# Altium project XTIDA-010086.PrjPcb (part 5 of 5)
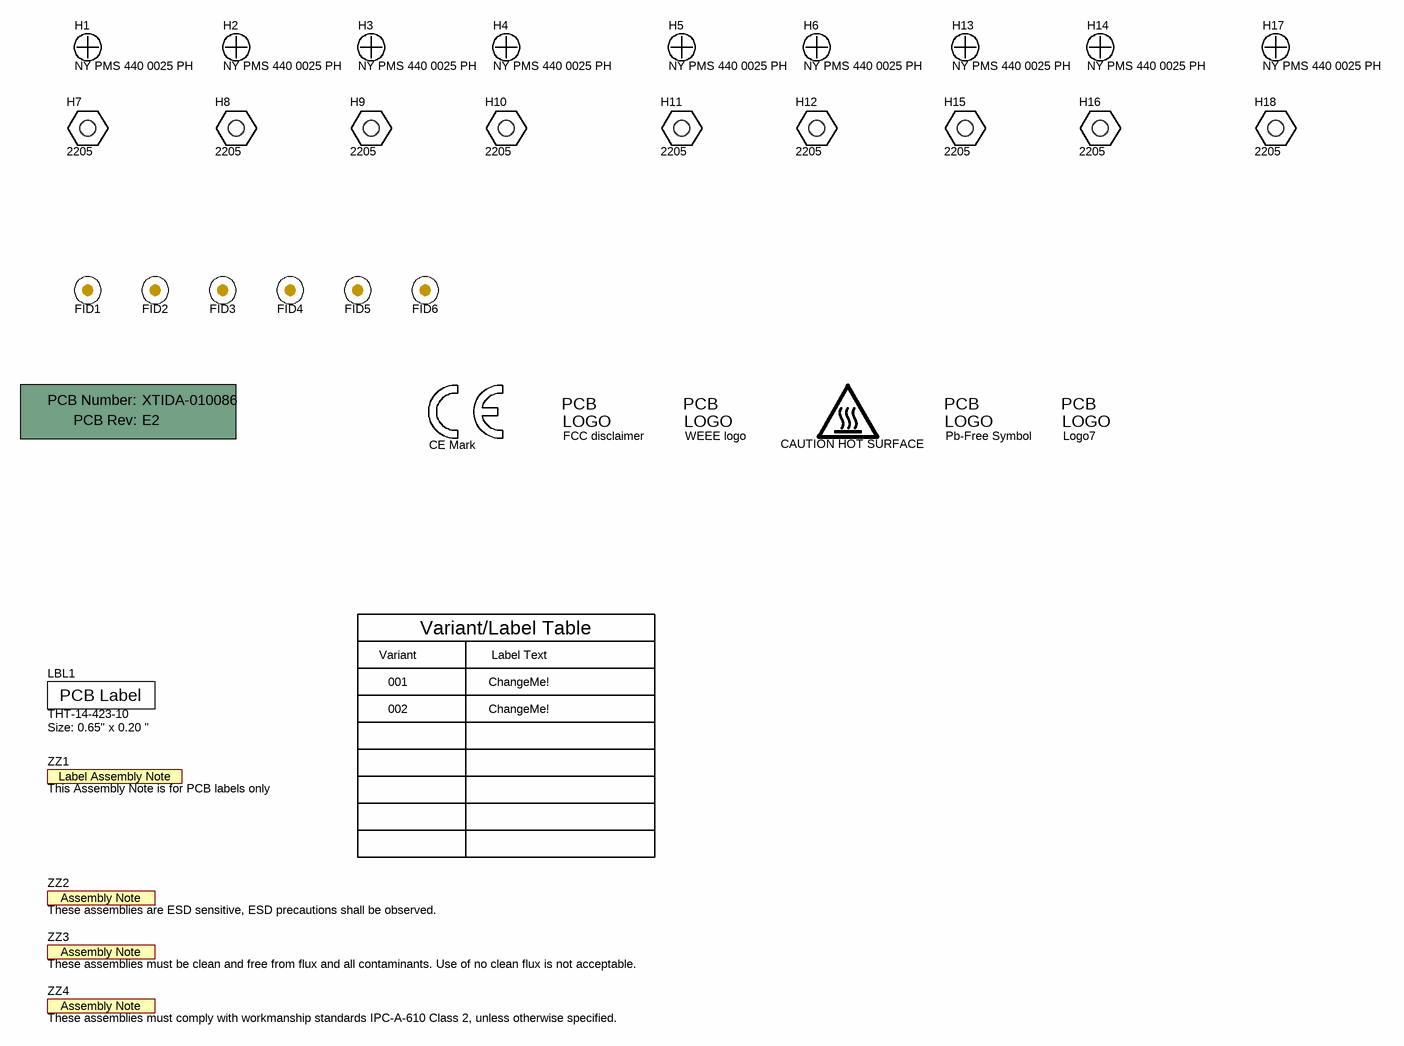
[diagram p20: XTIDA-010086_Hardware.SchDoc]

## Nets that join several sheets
2P5V: MAIN SHEET/Ch1 (C30_Ch1.1 C31_Ch1.1 U4_Ch1.3), MAIN SHEET/Ch2 (C30_Ch2.1 C31_Ch2.1 U4_Ch2.3), MAIN SHEET/Ch3 (C30_Ch3.1 C31_Ch3.1 U4_Ch3.3), MAIN SHEET/Ch4 (C30_Ch4.1 C31_Ch4.1 U4_Ch4.3), MAIN SHEET/Ch5 (C30_Ch5.1 C31_Ch5.1 U4_Ch5.3), MAIN SHEET/Ch6 (C30_Ch6.1 C31_Ch6.1 U4_Ch6.3), MAIN SHEET/Ch7 (C30_Ch7.1 C31_Ch7.1 U4_Ch7.3), MAIN SHEET/Ch8 (C30_Ch8.1 C31_Ch8.1 U4_Ch8.3), XTIDA-010086_Bias Power Supply (C130.1 R178.1 TP31.1 U7.5)
5V: MAIN SHEET/Ch1 (8 pins), MAIN SHEET/Ch2 (8 pins), MAIN SHEET/Ch3 (8 pins), MAIN SHEET/Ch4 (8 pins), MAIN SHEET/Ch5 (8 pins), MAIN SHEET/Ch6 (8 pins), MAIN SHEET/Ch7 (8 pins), MAIN SHEET/Ch8 (8 pins), XTIDA-010086_Bias Power Supply (5 pins)
5V_D: XTIDA-010086_Bias Power Supply (R163.1 R176.2 R183.1 TP33.1), XTIDA-010086_Control Card_28379 (6 pins)
10V: MAIN SHEET/Ch1 (9 pins), MAIN SHEET/Ch2 (9 pins), MAIN SHEET/Ch3 (9 pins), MAIN SHEET/Ch4 (9 pins), MAIN SHEET/Ch5 (9 pins), MAIN SHEET/Ch6 (9 pins), MAIN SHEET/Ch7 (9 pins), MAIN SHEET/Ch8 (9 pins), XTIDA-010086_Bias Power Supply (10 pins)
10V_Gate: MAIN SHEET/Ch1 (R8_Ch1.2), MAIN SHEET/Ch2 (R8_Ch2.2), MAIN SHEET/Ch3 (R8_Ch3.2), MAIN SHEET/Ch4 (R8_Ch4.2), MAIN SHEET/Ch5 (R8_Ch5.2), MAIN SHEET/Ch6 (R8_Ch6.2), MAIN SHEET/Ch7 (R8_Ch7.2), MAIN SHEET/Ch8 (R8_Ch8.2), XTIDA-010086_Bias Power Supply (8 pins)
12V_Out: XTIDA-010086_MAIN SHEET (6 pins), MAIN SHEET/Ch1 (L1_Ch1.1 TP4_Ch1.1), MAIN SHEET/Ch2 (L1_Ch2.1 TP4_Ch2.1), MAIN SHEET/Ch3 (L1_Ch3.1 TP4_Ch3.1), MAIN SHEET/Ch4 (L1_Ch4.1 TP4_Ch4.1), MAIN SHEET/Ch5 (L1_Ch5.1 TP4_Ch5.1), MAIN SHEET/Ch6 (L1_Ch6.1 TP4_Ch6.1), MAIN SHEET/Ch7 (L1_Ch7.1 TP4_Ch7.1), MAIN SHEET/Ch8 (L1_Ch8.1 TP4_Ch8.1), XTIDA-010086_Bias Power Supply (S3.2)
-2P5V: MAIN SHEET/Ch1 (C39_Ch1.1 C43_Ch1.1 U4_Ch1.2), MAIN SHEET/Ch2 (C39_Ch2.1 C43_Ch2.1 U4_Ch2.2), MAIN SHEET/Ch3 (C39_Ch3.1 C43_Ch3.1 U4_Ch3.2), MAIN SHEET/Ch4 (C39_Ch4.1 C43_Ch4.1 U4_Ch4.2), MAIN SHEET/Ch5 (C39_Ch5.1 C43_Ch5.1 U4_Ch5.2), MAIN SHEET/Ch6 (C39_Ch6.1 C43_Ch6.1 U4_Ch6.2), MAIN SHEET/Ch7 (C39_Ch7.1 C43_Ch7.1 U4_Ch7.2), MAIN SHEET/Ch8 (C39_Ch8.1 C43_Ch8.1 U4_Ch8.2), XTIDA-010086_Bias Power Supply (C133.1 C134.1 TP30.1 U8.5)
-5V: MAIN SHEET/Ch1 (17 pins), MAIN SHEET/Ch2 (17 pins), MAIN SHEET/Ch3 (17 pins), MAIN SHEET/Ch4 (17 pins), MAIN SHEET/Ch5 (17 pins), MAIN SHEET/Ch6 (17 pins), MAIN SHEET/Ch7 (17 pins), MAIN SHEET/Ch8 (17 pins), XTIDA-010086_Bias Power Supply (9 pins)
AGND: MAIN SHEET/Ch1 (44 pins), MAIN SHEET/Ch2 (44 pins), MAIN SHEET/Ch3 (44 pins), MAIN SHEET/Ch4 (44 pins), MAIN SHEET/Ch5 (44 pins), MAIN SHEET/Ch6 (44 pins), MAIN SHEET/Ch7 (44 pins), MAIN SHEET/Ch8 (44 pins), XTIDA-010086_ADC (35 pins), XTIDA-010086_Bias Power Supply (45 pins)
AVDD: XTIDA-010086_ADC (28 pins), XTIDA-010086_Bias Power Supply (8 pins)
DGND: MAIN SHEET/Ch1 (C14_Ch1.1 C122_Ch1.1 U2_Ch1.2 U24_Ch1.2), MAIN SHEET/Ch2 (C14_Ch2.1 C122_Ch2.1 U2_Ch2.2 U24_Ch2.2), MAIN SHEET/Ch3 (C14_Ch3.1 C122_Ch3.1 U2_Ch3.2 U24_Ch3.2), MAIN SHEET/Ch4 (C14_Ch4.1 C122_Ch4.1 U2_Ch4.2 U24_Ch4.2), MAIN SHEET/Ch5 (C14_Ch5.1 C122_Ch5.1 U2_Ch5.2 U24_Ch5.2), MAIN SHEET/Ch6 (C14_Ch6.1 C122_Ch6.1 U2_Ch6.2 U24_Ch6.2), MAIN SHEET/Ch7 (C14_Ch7.1 C122_Ch7.1 U2_Ch7.2 U24_Ch7.2), MAIN SHEET/Ch8 (C14_Ch8.1 C122_Ch8.1 U2_Ch8.2 U24_Ch8.2), XTIDA-010086_ADC (25 pins), XTIDA-010086_Bias Power Supply (12 pins), XTIDA-010086_Control Card_28379 (44 pins)
DVDD: MAIN SHEET/Ch1 (5 pins), MAIN SHEET/Ch2 (5 pins), MAIN SHEET/Ch3 (5 pins), MAIN SHEET/Ch4 (5 pins), MAIN SHEET/Ch5 (5 pins), MAIN SHEET/Ch6 (5 pins), MAIN SHEET/Ch7 (5 pins), MAIN SHEET/Ch8 (5 pins), XTIDA-010086_ADC (15 pins), XTIDA-010086_Bias Power Supply (6 pins), XTIDA-010086_Control Card_28379 (20 pins)
PGND: XTIDA-010086_MAIN SHEET (10 pins), MAIN SHEET/Ch1 (24 pins), MAIN SHEET/Ch2 (24 pins), MAIN SHEET/Ch3 (24 pins), MAIN SHEET/Ch4 (24 pins), MAIN SHEET/Ch5 (24 pins), MAIN SHEET/Ch6 (24 pins), MAIN SHEET/Ch7 (24 pins), MAIN SHEET/Ch8 (24 pins), XTIDA-010086_ADC (R152.1 R153.2), XTIDA-010086_Bias Power Supply (19 pins)
B+: MAIN SHEET/Ch1 (C52_Ch1.1 R10_Ch1.1 R14_Ch1.1 R64_Ch1.1), MAIN SHEET/Ch2 (C52_Ch2.1 R10_Ch2.1 R14_Ch2.1 R64_Ch2.1), MAIN SHEET/Ch3 (C52_Ch3.1 R10_Ch3.1 R14_Ch3.1 R64_Ch3.1), MAIN SHEET/Ch4 (C52_Ch4.1 R10_Ch4.1 R14_Ch4.1 R64_Ch4.1), MAIN SHEET/Ch5 (C52_Ch5.1 R10_Ch5.1 R14_Ch5.1 R64_Ch5.1), MAIN SHEET/Ch6 (C52_Ch6.1 R10_Ch6.1 R14_Ch6.1 R64_Ch6.1), MAIN SHEET/Ch7 (C52_Ch7.1 R10_Ch7.1 R14_Ch7.1 R64_Ch7.1), MAIN SHEET/Ch8 (C52_Ch8.1 R10_Ch8.1 R14_Ch8.1 R64_Ch8.1)
B-: MAIN SHEET/Ch1 (R17_Ch1.1 R20_Ch1.2 R70_Ch1.1), MAIN SHEET/Ch2 (R17_Ch2.1 R20_Ch2.2 R70_Ch2.1), MAIN SHEET/Ch3 (R17_Ch3.1 R20_Ch3.2 R70_Ch3.1), MAIN SHEET/Ch4 (R17_Ch4.1 R20_Ch4.2 R70_Ch4.1), MAIN SHEET/Ch5 (R17_Ch5.1 R20_Ch5.2 R70_Ch5.1), MAIN SHEET/Ch6 (R17_Ch6.1 R20_Ch6.2 R70_Ch6.1), MAIN SHEET/Ch7 (R17_Ch7.1 R20_Ch7.2 R70_Ch7.1), MAIN SHEET/Ch8 (R17_Ch8.1 R20_Ch8.2 R70_Ch8.1)
C2000_CLK: XTIDA-010086_ADC (R95.2 R126.2 TP11.1 U28.2), XTIDA-010086_Control Card_28379 (R292.1)
CS1: XTIDA-010086_ADC (R108.1 R112.2 TP16.1), XTIDA-010086_Control Card_28379 (R280.1)
CS2: XTIDA-010086_ADC (R139.1 R143.2 TP22.1), XTIDA-010086_Control Card_28379 (R285.2)
CS+: MAIN SHEET/Ch1 (5 pins), MAIN SHEET/Ch2 (5 pins), MAIN SHEET/Ch3 (5 pins), MAIN SHEET/Ch4 (5 pins), MAIN SHEET/Ch5 (5 pins), MAIN SHEET/Ch6 (5 pins), MAIN SHEET/Ch7 (5 pins), MAIN SHEET/Ch8 (5 pins)
CS-: MAIN SHEET/Ch1 (5 pins), MAIN SHEET/Ch2 (5 pins), MAIN SHEET/Ch3 (5 pins), MAIN SHEET/Ch4 (5 pins), MAIN SHEET/Ch5 (5 pins), MAIN SHEET/Ch6 (5 pins), MAIN SHEET/Ch7 (5 pins), MAIN SHEET/Ch8 (5 pins)
DACA: MAIN SHEET/Ch1 (R192_Ch1.1 R218_Ch1.2), MAIN SHEET/Ch2 (R192_Ch2.1 R218_Ch2.2), MAIN SHEET/Ch3 (R192_Ch3.1 R218_Ch3.2), MAIN SHEET/Ch4 (R192_Ch4.1 R218_Ch4.2), MAIN SHEET/Ch5 (R192_Ch5.1 R218_Ch5.2), MAIN SHEET/Ch6 (R192_Ch6.1 R218_Ch6.2), MAIN SHEET/Ch7 (R192_Ch7.1 R218_Ch7.2), MAIN SHEET/Ch8 (R192_Ch8.1 R218_Ch8.2), XTIDA-010086_Control Card_28379 (R221.1)
DIN1: XTIDA-010086_ADC (R102.2 TP12.1), XTIDA-010086_Control Card_28379 (R277.1)
DIN2: XTIDA-010086_ADC (R133.2 TP18.1), XTIDA-010086_Control Card_28379 (R284.1)
DIR: MAIN SHEET/Ch1 (R162_Ch1.1 U29_Ch1.9 U29_Ch1.10 U29_Ch1.11), MAIN SHEET/Ch2 (R162_Ch2.1 U29_Ch2.9 U29_Ch2.10 U29_Ch2.11), MAIN SHEET/Ch3 (R162_Ch3.1 U29_Ch3.9 U29_Ch3.10 U29_Ch3.11), MAIN SHEET/Ch4 (R162_Ch4.1 U29_Ch4.9 U29_Ch4.10 U29_Ch4.11), MAIN SHEET/Ch5 (R162_Ch5.1 U29_Ch5.9 U29_Ch5.10 U29_Ch5.11), MAIN SHEET/Ch6 (R162_Ch6.1 U29_Ch6.9 U29_Ch6.10 U29_Ch6.11), MAIN SHEET/Ch7 (R162_Ch7.1 U29_Ch7.9 U29_Ch7.10 U29_Ch7.11), MAIN SHEET/Ch8 (R162_Ch8.1 U29_Ch8.9 U29_Ch8.10 U29_Ch8.11), XTIDA-010086_Control Card_28379 (R58.1)
DOUT1: XTIDA-010086_ADC (R105.2 TP13.1), XTIDA-010086_Control Card_28379 (R279.1)
DOUT2: XTIDA-010086_ADC (R136.2 TP19.1), XTIDA-010086_Control Card_28379 (R286.1)
DRDY1: XTIDA-010086_ADC (R110.2 TP15.1), XTIDA-010086_Control Card_28379 (R278.1)
DRDY2: XTIDA-010086_ADC (R141.2 TP21.1), XTIDA-010086_Control Card_28379 (R283.1)
EPWM_A: MAIN SHEET/Ch1 (R216_Ch1.2 U24_Ch1.6), MAIN SHEET/Ch2 (R216_Ch2.2 U24_Ch2.6), MAIN SHEET/Ch3 (R216_Ch3.2 U24_Ch3.6), MAIN SHEET/Ch4 (R216_Ch4.2 U24_Ch4.6), MAIN SHEET/Ch5 (R216_Ch5.2 U24_Ch5.6), MAIN SHEET/Ch6 (R216_Ch6.2 U24_Ch6.6), MAIN SHEET/Ch7 (R216_Ch7.2 U24_Ch7.6), MAIN SHEET/Ch8 (R216_Ch8.2 U24_Ch8.6)
EPWM_B: MAIN SHEET/Ch1 (R217_Ch1.2 U2_Ch1.6), MAIN SHEET/Ch2 (R217_Ch2.2 U2_Ch2.6), MAIN SHEET/Ch3 (R217_Ch3.2 U2_Ch3.6), MAIN SHEET/Ch4 (R217_Ch4.2 U2_Ch4.6), MAIN SHEET/Ch5 (R217_Ch5.2 U2_Ch5.6), MAIN SHEET/Ch6 (R217_Ch6.2 U2_Ch6.6), MAIN SHEET/Ch7 (R217_Ch7.2 U2_Ch7.6), MAIN SHEET/Ch8 (R217_Ch8.2 U2_Ch8.6)
H-Drive: MAIN SHEET/Ch1 (D3_Ch1.1 R11_Ch1.2 U1_Ch1.7), MAIN SHEET/Ch2 (D3_Ch2.1 R11_Ch2.2 U1_Ch2.7), MAIN SHEET/Ch3 (D3_Ch3.1 R11_Ch3.2 U1_Ch3.7), MAIN SHEET/Ch4 (D3_Ch4.1 R11_Ch4.2 U1_Ch4.7), MAIN SHEET/Ch5 (D3_Ch5.1 R11_Ch5.2 U1_Ch5.7), MAIN SHEET/Ch6 (D3_Ch6.1 R11_Ch6.2 U1_Ch6.7), MAIN SHEET/Ch7 (D3_Ch7.1 R11_Ch7.2 U1_Ch7.7), MAIN SHEET/Ch8 (D3_Ch8.1 R11_Ch8.2 U1_Ch8.7)
HDrive: MAIN SHEET/Ch1 (Q1_Ch1.4 R11_Ch1.1 R18_Ch1.2 R19_Ch1.2), MAIN SHEET/Ch2 (Q1_Ch2.4 R11_Ch2.1 R18_Ch2.2 R19_Ch2.2), MAIN SHEET/Ch3 (Q1_Ch3.4 R11_Ch3.1 R18_Ch3.2 R19_Ch3.2), MAIN SHEET/Ch4 (Q1_Ch4.4 R11_Ch4.1 R18_Ch4.2 R19_Ch4.2), MAIN SHEET/Ch5 (Q1_Ch5.4 R11_Ch5.1 R18_Ch5.2 R19_Ch5.2), MAIN SHEET/Ch6 (Q1_Ch6.4 R11_Ch6.1 R18_Ch6.2 R19_Ch6.2), MAIN SHEET/Ch7 (Q1_Ch7.4 R11_Ch7.1 R18_Ch7.2 R19_Ch7.2), MAIN SHEET/Ch8 (Q1_Ch8.4 R11_Ch8.1 R18_Ch8.2 R19_Ch8.2)
Interrupt: MAIN SHEET/Ch1 (5 pins), MAIN SHEET/Ch2 (5 pins), MAIN SHEET/Ch3 (5 pins), MAIN SHEET/Ch4 (5 pins), MAIN SHEET/Ch5 (5 pins), MAIN SHEET/Ch6 (5 pins), MAIN SHEET/Ch7 (5 pins), MAIN SHEET/Ch8 (5 pins)
IoutN: MAIN SHEET/Ch1 (C28_Ch1.2 R40_Ch1.2 TP8_Ch1.1), MAIN SHEET/Ch2 (C28_Ch2.2 R40_Ch2.2 TP8_Ch2.1), MAIN SHEET/Ch3 (C28_Ch3.2 R40_Ch3.2 TP8_Ch3.1), MAIN SHEET/Ch4 (C28_Ch4.2 R40_Ch4.2 TP8_Ch4.1), MAIN SHEET/Ch5 (C28_Ch5.2 R40_Ch5.2 TP8_Ch5.1), MAIN SHEET/Ch6 (C28_Ch6.2 R40_Ch6.2 TP8_Ch6.1), MAIN SHEET/Ch7 (C28_Ch7.2 R40_Ch7.2 TP8_Ch7.1), MAIN SHEET/Ch8 (C28_Ch8.2 R40_Ch8.2 TP8_Ch8.1)
IoutP: MAIN SHEET/Ch1 (C28_Ch1.1 R36_Ch1.2 R186_Ch1.2 TP7_Ch1.1), MAIN SHEET/Ch2 (C28_Ch2.1 R36_Ch2.2 R186_Ch2.2 TP7_Ch2.1), MAIN SHEET/Ch3 (C28_Ch3.1 R36_Ch3.2 R186_Ch3.2 TP7_Ch3.1), MAIN SHEET/Ch4 (C28_Ch4.1 R36_Ch4.2 R186_Ch4.2 TP7_Ch4.1), MAIN SHEET/Ch5 (C28_Ch5.1 R36_Ch5.2 R186_Ch5.2 TP7_Ch5.1), MAIN SHEET/Ch6 (C28_Ch6.1 R36_Ch6.2 R186_Ch6.2 TP7_Ch6.1), MAIN SHEET/Ch7 (C28_Ch7.1 R36_Ch7.2 R186_Ch7.2 TP7_Ch7.1), MAIN SHEET/Ch8 (C28_Ch8.1 R36_Ch8.2 R186_Ch8.2 TP7_Ch8.1)
IoutP1: XTIDA-010086_ADC (D12.2 R90.1 U13.1), XTIDA-010086_Control Card_28379 (R245.1)
IoutP2: XTIDA-010086_ADC (D19.2 R94.1 U13.5), XTIDA-010086_Control Card_28379 (R246.1)
IoutP3: XTIDA-010086_ADC (D21.2 R101.1 U14.5), XTIDA-010086_Control Card_28379 (R249.1)
IoutP4: XTIDA-010086_ADC (D23.2 R111.1 U14.1), XTIDA-010086_Control Card_28379 (R250.1)
IoutP5: XTIDA-010086_ADC (D25.2 R121.1 U17.1), XTIDA-010086_Control Card_28379 (R253.1)
IoutP6: XTIDA-010086_ADC (D27.2 R125.1 U17.5), XTIDA-010086_Control Card_28379 (R254.1)
IoutP7: XTIDA-010086_ADC (D29.2 R132.1 U18.5), XTIDA-010086_Control Card_28379 (R257.1)
IoutP8: XTIDA-010086_ADC (D31.2 R142.1 U18.1), XTIDA-010086_Control Card_28379 (R258.1)
L-Drive: MAIN SHEET/Ch1 (D4_Ch1.1 R21_Ch1.2 U1_Ch1.5), MAIN SHEET/Ch2 (D4_Ch2.1 R21_Ch2.2 U1_Ch2.5), MAIN SHEET/Ch3 (D4_Ch3.1 R21_Ch3.2 U1_Ch3.5), MAIN SHEET/Ch4 (D4_Ch4.1 R21_Ch4.2 U1_Ch4.5), MAIN SHEET/Ch5 (D4_Ch5.1 R21_Ch5.2 U1_Ch5.5), MAIN SHEET/Ch6 (D4_Ch6.1 R21_Ch6.2 U1_Ch6.5), MAIN SHEET/Ch7 (D4_Ch7.1 R21_Ch7.2 U1_Ch7.5), MAIN SHEET/Ch8 (D4_Ch8.1 R21_Ch8.2 U1_Ch8.5)
LDrive: MAIN SHEET/Ch1 (Q7_Ch1.4 R21_Ch1.1 R24_Ch1.2 R25_Ch1.2), MAIN SHEET/Ch2 (Q7_Ch2.4 R21_Ch2.1 R24_Ch2.2 R25_Ch2.2), MAIN SHEET/Ch3 (Q7_Ch3.4 R21_Ch3.1 R24_Ch3.2 R25_Ch3.2), MAIN SHEET/Ch4 (Q7_Ch4.4 R21_Ch4.1 R24_Ch4.2 R25_Ch4.2), MAIN SHEET/Ch5 (Q7_Ch5.4 R21_Ch5.1 R24_Ch5.2 R25_Ch5.2), MAIN SHEET/Ch6 (Q7_Ch6.4 R21_Ch6.1 R24_Ch6.2 R25_Ch6.2), MAIN SHEET/Ch7 (Q7_Ch7.4 R21_Ch7.1 R24_Ch7.2 R25_Ch7.2), MAIN SHEET/Ch8 (Q7_Ch8.4 R21_Ch8.1 R24_Ch8.2 R25_Ch8.2)
Protection: MAIN SHEET/Ch1 (R75_Ch1.1 R175_Ch1.1 U9_Ch1.2 U29_Ch1.14), MAIN SHEET/Ch2 (R75_Ch2.1 R175_Ch2.1 U9_Ch2.2 U29_Ch2.14), MAIN SHEET/Ch3 (R75_Ch3.1 R175_Ch3.1 U9_Ch3.2 U29_Ch3.14), MAIN SHEET/Ch4 (R75_Ch4.1 R175_Ch4.1 U9_Ch4.2 U29_Ch4.14), MAIN SHEET/Ch5 (R75_Ch5.1 R175_Ch5.1 U9_Ch5.2 U29_Ch5.14), MAIN SHEET/Ch6 (R75_Ch6.1 R175_Ch6.1 U9_Ch6.2 U29_Ch6.14), MAIN SHEET/Ch7 (R75_Ch7.1 R175_Ch7.1 U9_Ch7.2 U29_Ch7.14), MAIN SHEET/Ch8 (R75_Ch8.1 R175_Ch8.1 U9_Ch8.2 U29_Ch8.14)
RESET1: XTIDA-010086_ADC (11 pins), XTIDA-010086_Control Card_28379 (R282.1)
SCLK1: XTIDA-010086_ADC (R106.2 TP14.1), XTIDA-010086_Control Card_28379 (R298.1)
SCLK2: XTIDA-010086_ADC (R137.2 TP20.1), XTIDA-010086_Control Card_28379 (R288.1)
SW: MAIN SHEET/Ch1 (16 pins), MAIN SHEET/Ch2 (16 pins), MAIN SHEET/Ch3 (16 pins), MAIN SHEET/Ch4 (16 pins), MAIN SHEET/Ch5 (16 pins), MAIN SHEET/Ch6 (16 pins), MAIN SHEET/Ch7 (16 pins), MAIN SHEET/Ch8 (16 pins)
VoutN: MAIN SHEET/Ch1 (C51_Ch1.2 R74_Ch1.2 TP10_Ch1.1), MAIN SHEET/Ch2 (C51_Ch2.2 R74_Ch2.2 TP10_Ch2.1), MAIN SHEET/Ch3 (C51_Ch3.2 R74_Ch3.2 TP10_Ch3.1), MAIN SHEET/Ch4 (C51_Ch4.2 R74_Ch4.2 TP10_Ch4.1), MAIN SHEET/Ch5 (C51_Ch5.2 R74_Ch5.2 TP10_Ch5.1), MAIN SHEET/Ch6 (C51_Ch6.2 R74_Ch6.2 TP10_Ch6.1), MAIN SHEET/Ch7 (C51_Ch7.2 R74_Ch7.2 TP10_Ch7.1), MAIN SHEET/Ch8 (C51_Ch8.2 R74_Ch8.2 TP10_Ch8.1)
VoutP: MAIN SHEET/Ch1 (C51_Ch1.1 R68_Ch1.2 TP9_Ch1.1), MAIN SHEET/Ch2 (C51_Ch2.1 R68_Ch2.2 TP9_Ch2.1), MAIN SHEET/Ch3 (C51_Ch3.1 R68_Ch3.2 TP9_Ch3.1), MAIN SHEET/Ch4 (C51_Ch4.1 R68_Ch4.2 TP9_Ch4.1), MAIN SHEET/Ch5 (C51_Ch5.1 R68_Ch5.2 TP9_Ch5.1), MAIN SHEET/Ch6 (C51_Ch6.1 R68_Ch6.2 TP9_Ch6.1), MAIN SHEET/Ch7 (C51_Ch7.1 R68_Ch7.2 TP9_Ch7.1), MAIN SHEET/Ch8 (C51_Ch8.1 R68_Ch8.2 TP9_Ch8.1)
VoutP1: XTIDA-010086_ADC (D16.2 R93.1 U13.3), XTIDA-010086_Control Card_28379 (R247.1)
VoutP2: XTIDA-010086_ADC (D20.2 R100.1 U13.4), XTIDA-010086_Control Card_28379 (R248.1)
VoutP3: XTIDA-010086_ADC (D22.2 R107.1 U14.4), XTIDA-010086_Control Card_28379 (R251.1)
VoutP4: XTIDA-010086_ADC (D24.2 R117.1 U14.3), XTIDA-010086_Control Card_28379 (R252.1)
VoutP5: XTIDA-010086_ADC (D26.2 R124.1 U17.3), XTIDA-010086_Control Card_28379 (R255.1)
VoutP6: XTIDA-010086_ADC (D28.2 R131.1 U17.4), XTIDA-010086_Control Card_28379 (R256.1)
VoutP7: XTIDA-010086_ADC (D30.2 R138.1 U18.4), XTIDA-010086_Control Card_28379 (R259.1)
VoutP8: XTIDA-010086_ADC (D32.2 R148.1 U18.3), XTIDA-010086_Control Card_28379 (R260.1)

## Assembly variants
001: not fitted C2_Ch1 C2_Ch2 C2_Ch3 C2_Ch4 C2_Ch5 C2_Ch6 C2_Ch7 C2_Ch8 D12 D16 D19 D20 D21 D22 D23 D24 D25 D26 D27 D28 D29 D30 D31 D32 FID1 FID2 FID3 FID4 FID5 FID6 R4_Ch1 R4_Ch2 R4_Ch3 R4_Ch4 R4_Ch5 R4_Ch6 R4_Ch7 R4_Ch8 R14_Ch1 R14_Ch2 R14_Ch3 R14_Ch4 R14_Ch5 R14_Ch6 R14_Ch7 R14_Ch8 R15_Ch1 R15_Ch2 R15_Ch3 R15_Ch4 R15_Ch5 R15_Ch6 R15_Ch7 R15_Ch8 R16_Ch1 R16_Ch2 R16_Ch3 R16_Ch4 R16_Ch5 R16_Ch6 R16_Ch7 R16_Ch8 R17_Ch1 R17_Ch2 R17_Ch3 R17_Ch4 R17_Ch5 R17_Ch6 R17_Ch7 R17_Ch8 R41_Ch1 R41_Ch2 R41_Ch3 R41_Ch4 R41_Ch5 R41_Ch6 R41_Ch7 R41_Ch8 R43_Ch1 R43_Ch2 R43_Ch3 R43_Ch4 R43_Ch5 R43_Ch6 R43_Ch7 R43_Ch8 R45_Ch1 R45_Ch2 R45_Ch3 R45_Ch4 R45_Ch5 R45_Ch6 R45_Ch7 R45_Ch8 R47_Ch1 R47_Ch2 R47_Ch3 R47_Ch4 R47_Ch5 R47_Ch6 R47_Ch7 R47_Ch8 R48_Ch1 R48_Ch2 R48_Ch3 R48_Ch4 R48_Ch5 R48_Ch6 R48_Ch7 R48_Ch8 R55 R56 R57 R95 R126 R186_Ch1 R186_Ch2 R186_Ch3 R186_Ch4 R186_Ch5 R186_Ch6 R186_Ch7 R186_Ch8 R187 R188 R189 R203 R245 R246 R247 R248 R249 R250 R251 R252 R253 R254 R255 R256 R257 R258 R259 R260 R292 U2_Ch1 U2_Ch2 U2_Ch3 U2_Ch4 U2_Ch5 U2_Ch6 U2_Ch7 U2_Ch8 U4_Ch1 U4_Ch2 U4_Ch3 U4_Ch4 U4_Ch5 U4_Ch6 U4_Ch7 U4_Ch8 U5_Ch1 U5_Ch2 U5_Ch3 U5_Ch4 U5_Ch5 U5_Ch6 U5_Ch7 U5_Ch8 U6_Ch1 U6_Ch2 U6_Ch3 U6_Ch4 U6_Ch5 U6_Ch6 U6_Ch7 U6_Ch8 U9_Ch1 U9_Ch2 U9_Ch3 U9_Ch4 U9_Ch5 U9_Ch6 U9_Ch7 U9_Ch8 U11 U13 U14 U17 U18 U24_Ch1 U24_Ch2 U24_Ch3 U24_Ch4 U24_Ch5 U24_Ch6 U24_Ch7 U24_Ch8 U26 U27 U28 U29_Ch1 U29_Ch2 U29_Ch3 U29_Ch4 U29_Ch5 U29_Ch6 U29_Ch7 U29_Ch8 U30_Ch1 U30_Ch2 U30_Ch3 U30_Ch4 U30_Ch5 U30_Ch6 U30_Ch7 U30_Ch8 U32_Ch1 U32_Ch2 U32_Ch3 U32_Ch4 U32_Ch5 U32_Ch6 U32_Ch7 U32_Ch8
